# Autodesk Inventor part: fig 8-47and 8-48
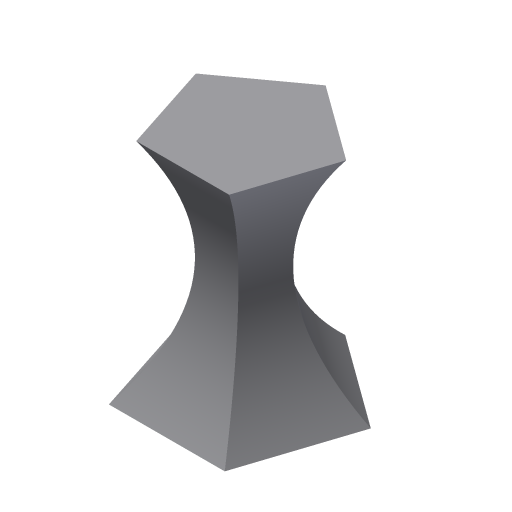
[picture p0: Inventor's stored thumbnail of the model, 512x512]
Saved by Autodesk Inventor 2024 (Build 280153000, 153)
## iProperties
Shininess: 64.0
Length Units: 11269
Angle Units: 11279
Time Units: 11290
Mass Units: 11283
Length Display Precision: 3
Angle Display Precision: 2
Compacted: True
Part Number: fig 8-47and 8-48
Document SubType Name: Modeling
Created: 2002-12
Designer: deepak
Density: 1 g/cm^3
Material: Generic
Appearance: Default
Density: 0.0
Volumn: 0.0
Area: 0.0
PropertySet Name: Model Information
Control State: 0
Master: False
Checked Out: False
Author: deepak
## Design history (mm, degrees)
sketch "Sketch1"
  geometry: L1 (0, 21.819)-(20.751, 6.743); L2 (20.751, 6.743)-(12.825, -17.652); L3 (12.825, -17.652)-(-12.825, -17.652); L4 (-12.825, -17.652)-(-20.751, 6.743); L5 (-20.751, 6.743)-(0, 21.819); 1 further point
  constraints: 10 end point, 9 other
workplane "Work Plane1"
sketch "Sketch2"
  geometry: L1 (0, 8.24)-(7.836, 2.546); L2 (7.836, 2.546)-(4.843, -6.666); L3 (4.843, -6.666)-(-4.843, -6.666); L4 (-4.843, -6.666)-(-7.836, 2.546); L5 (-7.836, 2.546)-(0, 8.24); 1 further point
  constraints: 10 end point, 9 other
workplane "Work Plane2"
sketch "Sketch3"
  geometry: L1 (0, 17.494)-(16.637, 5.406); L2 (16.637, 5.406)-(10.283, -14.153); L3 (10.283, -14.153)-(-10.283, -14.153); L4 (-10.283, -14.153)-(-16.637, 5.406); L5 (-16.637, 5.406)-(0, 17.494); 1 further point
  constraints: 10 end point, 9 other
loft "Loft4" sketch "Sketch3" dims "d20" = 0, "d21" = 90 deg, "d22" = 0, "d23" = 90 deg, "d24" = 0, "d25" = 90 deg
body "Solid1"
other parameters: "d0" = 25, "d1" = 25
